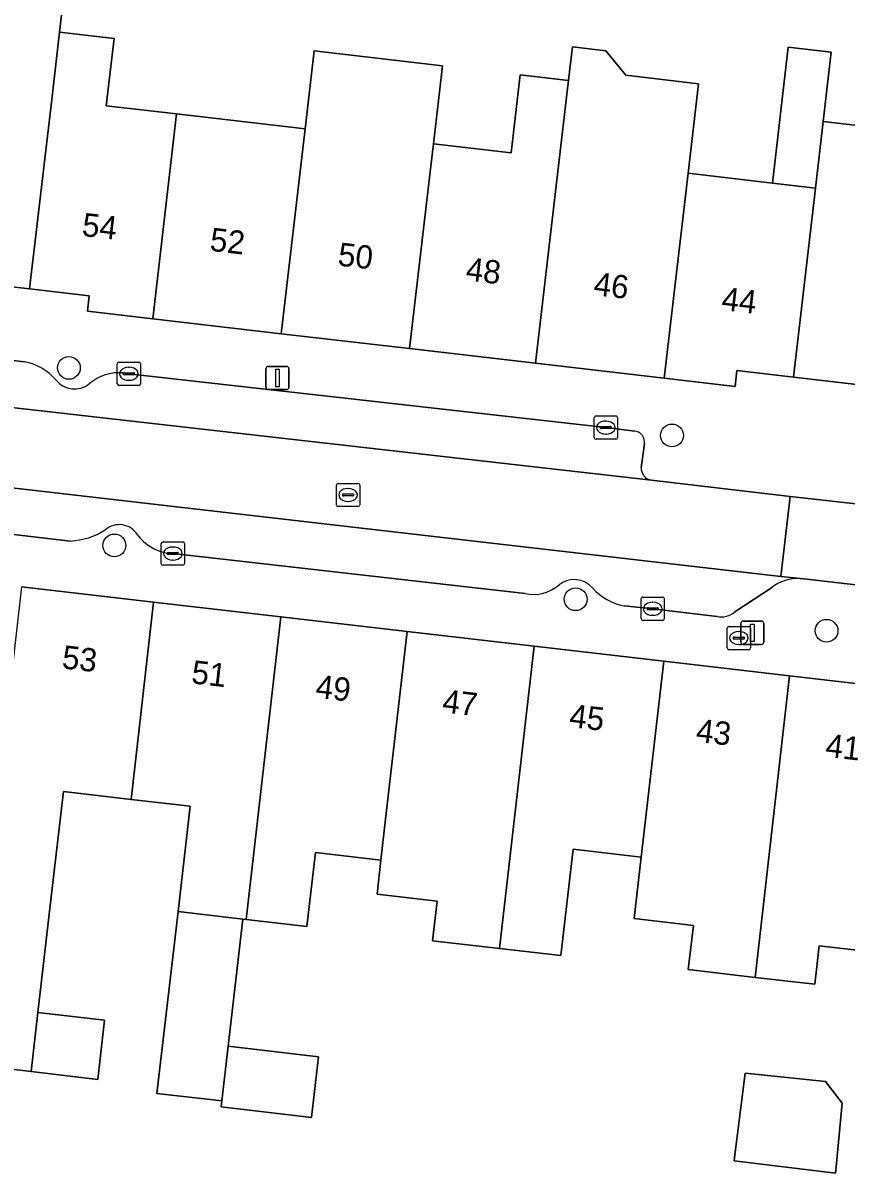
# Model space of a CAD drawing. Extents: x 161692 to 162379, y 380760 to 381678.
# Drawn here: x 161868.24 to 161903.6, y 381375.82 to 381425.22 of the extents above; entities that cross this region are included whole.
import ezdxf

# ---------------------------------------------------------------- set-up
doc = ezdxf.new("R2010")
doc.units = 0
for name, color, linetype in [('IMGEO_Boom', 7, 'Continuous'), ('IMGEO_Brandkraan', 7, 'Continuous'), ('IMGEO_Erf', 7, 'Continuous'), ('IMGEO_Kolk', 7, 'Continuous'), ('IMGEO_Lichtmast', 7, 'Continuous'), ('IMGEO_Pand', 7, 'Continuous'), ('IMGEO_Pand_nummerreeks', 7, 'Continuous'), ('IMGEO_Parkeervlak_open', 7, 'Continuous'), ('IMGEO_Rijbaan_lokaal_open', 7, 'Continuous'), ('IMGEO_Rioolput', 7, 'Continuous'), ('IMGEO_Voetpad_open', 7, 'Continuous')]:
    doc.layers.add(name, color=color, linetype=linetype)

msp = doc.modelspace()

# ---------------------------------------------------------------- linework, layer by layer
at = {"layer": 'IMGEO_Boom'}
for centre in [(161870.211, 381410.403), (161896.121, 381407.499), (161872.165, 381402.777), (161891.981, 381400.464), (161902.76, 381399.11)]:
    msp.add_circle(centre, 0.489, dxfattribs=at)
at = {"layer": 'IMGEO_Brandkraan'}
for p, q in [((161898.494, 381398.371), (161898.494, 381399.223)), ((161898.569, 381399.297), (161899.421, 381399.297)), ((161898.982, 381399.077), (161899.007, 381399.077)), ((161899.495, 381399.223), (161899.495, 381398.371)), ((161898.753, 381398.791), (161898.753, 381398.803)), ((161899.191, 381398.754), (161898.793, 381398.754)), ((161898.796, 381398.84), (161899.194, 381398.84)), ((161899.005, 381398.517), (161898.98, 381398.517)), ((161899.237, 381398.803), (161899.237, 381398.791)), ((161899.421, 381398.297), (161898.569, 381398.297))]:
    msp.add_line(p, q, dxfattribs=at)
for points in [[(161898.494, 381398.371), (161898.494, 381399.223)], [(161898.569, 381399.297), (161899.421, 381399.297)], [(161899.495, 381399.223), (161899.495, 381398.371)], [(161899.421, 381398.297), (161898.569, 381398.297)]]:
    msp.add_lwpolyline(points, dxfattribs=at)
for centre, radius, start, end in [((161898.571, 381399.221), 0.0765, 91.552, 178.448), ((161898.571, 381399.221), 0.0765, 91.552, 178.448), ((161899.419, 381399.221), 0.0765, 1.552, 88.448), ((161899.419, 381399.221), 0.0765, 1.552, 88.448), ((161898.793, 381398.8), 0.0403, 85.8775, 175.7526), ((161898.79, 381398.79), 0.0366, 178.938, 274.7102), ((161899.194, 381398.797), 0.043, 264.8664, 352.4533), ((161899.198, 381398.802), 0.0386, 1.7309, 96.639), ((161898.571, 381398.373), 0.0765, 181.552, 268.448), ((161898.571, 381398.373), 0.0765, 181.552, 268.448), ((161899.419, 381398.373), 0.0765, 271.552, 358.448), ((161899.419, 381398.373), 0.0765, 271.552, 358.448)]:
    msp.add_arc(centre, radius, start, end, dxfattribs=at)
for centre, major_axis, ratio, start_param, end_param in [((161898.981, 381398.797), (-0.387, 0.002), 0.722429, 4.712389, 7.853982), ((161899.006, 381398.797), (-0.39, 0.002), 0.717154, 1.570796, 4.712389)]:
    msp.add_ellipse(centre, major_axis=major_axis, ratio=ratio, start_param=start_param, end_param=end_param, dxfattribs=at)
at = {"layer": 'IMGEO_Erf'}
for points in [[(161870.722, 381432.685), (161869.807, 381424.816), (161872.151, 381424.544), (161871.816, 381421.661), (161874.839, 381421.31), (161880.359, 381420.669), (161880.749, 381424.017), (161886.262, 381423.376), (161885.872, 381420.029), (161889.213, 381419.641), (161889.601, 381422.988), (161891.674, 381422.747), (161891.733, 381423.252), (161891.842, 381424.189), (161893.278, 381424.022), (161894.138, 381422.973), (161897.26, 381422.61), (161896.812, 381418.759), (161900.436, 381418.338), (161901.114, 381424.178), (161902.96, 381423.964), (161902.614, 381420.985), (161907.924, 381420.369)], [(161905.321, 381385.248), (161902.447, 381385.58), (161902.256, 381383.926), (161899.696, 381384.222), (161896.821, 381384.555), (161897.04, 381386.451), (161894.501, 381386.744), (161894.802, 381389.384), (161891.877, 381389.723), (161891.348, 381385.157), (161888.713, 381385.462), (161885.831, 381385.796), (161886.027, 381387.493), (161883.448, 381387.792), (161883.616, 381389.255), (161880.801, 381389.58), (161880.433, 381386.404), (161877.827, 381386.706), (161877.685, 381386.722), (161877.054, 381381.264), (161880.94, 381380.813), (161880.637, 381378.203), (161876.751, 381378.654), (161876.781, 381378.914), (161873.996, 381379.236), (161874.9, 381387.045), (161875.424, 381391.571), (161872.88, 381391.865), (161869.978, 381392.201), (161869.454, 381387.674), (161868.879, 381382.71), (161871.743, 381382.378), (161871.449, 381379.84), (161868.586, 381380.179), (161865.833, 381380.505)]]:
    msp.add_lwpolyline(points, dxfattribs=at)
msp.add_lwpolyline([(161898.792, 381376.334), (161898.826, 381376.604), (161898.91, 381377.277), (161899.263, 381380.101), (161902.715, 381379.751), (161903.428, 381378.818), (161903.173, 381376.09), (161903.147, 381375.818)], close=True, dxfattribs=at)
at = {"layer": 'IMGEO_Kolk'}
for p, q in [((161872.288, 381409.722), (161872.288, 381410.574)), ((161872.363, 381410.648), (161873.215, 381410.648)), ((161872.776, 381410.428), (161872.801, 381410.428)), ((161873.289, 381410.574), (161873.289, 381409.722)), ((161872.547, 381410.142), (161872.547, 381410.154)), ((161872.985, 381410.105), (161872.587, 381410.105)), ((161872.59, 381410.191), (161872.988, 381410.191)), ((161872.799, 381409.868), (161872.774, 381409.868)), ((161873.031, 381410.154), (161873.031, 381410.142)), ((161873.215, 381409.648), (161872.363, 381409.648)), ((161892.858, 381408.336), (161893.71, 381408.336)), ((161892.783, 381407.41), (161892.783, 381408.262)), ((161893.042, 381407.83), (161893.042, 381407.842)), ((161893.085, 381407.879), (161893.483, 381407.879)), ((161893.271, 381408.116), (161893.296, 381408.116)), ((161893.526, 381407.842), (161893.526, 381407.83)), ((161893.784, 381408.262), (161893.784, 381407.41)), ((161893.71, 381407.336), (161892.858, 381407.336)), ((161893.48, 381407.793), (161893.082, 381407.793)), ((161893.294, 381407.556), (161893.269, 381407.556)), ((161874.255, 381402.927), (161875.107, 381402.927)), ((161874.18, 381402.001), (161874.18, 381402.853)), ((161874.439, 381402.421), (161874.439, 381402.433)), ((161874.877, 381402.384), (161874.479, 381402.384)), ((161874.482, 381402.47), (161874.88, 381402.47)), ((161874.668, 381402.707), (161874.693, 381402.707)), ((161874.923, 381402.433), (161874.923, 381402.421)), ((161875.181, 381402.853), (161875.181, 381402.001)), ((161875.107, 381401.927), (161874.255, 381401.927)), ((161874.691, 381402.147), (161874.666, 381402.147)), ((161894.791, 381399.63), (161894.791, 381400.482)), ((161894.866, 381400.556), (161895.718, 381400.556)), ((161895.792, 381400.482), (161895.792, 381399.63)), ((161895.05, 381400.05), (161895.05, 381400.062)), ((161895.488, 381400.013), (161895.09, 381400.013)), ((161895.093, 381400.099), (161895.491, 381400.099)), ((161895.279, 381400.336), (161895.304, 381400.336)), ((161895.534, 381400.062), (161895.534, 381400.05)), ((161895.718, 381399.556), (161894.866, 381399.556)), ((161895.302, 381399.776), (161895.277, 381399.776))]:
    msp.add_line(p, q, dxfattribs=at)
for points in [[(161872.288, 381409.722), (161872.288, 381410.574)], [(161872.363, 381410.648), (161873.215, 381410.648)], [(161873.289, 381410.574), (161873.289, 381409.722)], [(161873.215, 381409.648), (161872.363, 381409.648)], [(161892.858, 381408.336), (161893.71, 381408.336)], [(161892.783, 381407.41), (161892.783, 381408.262)], [(161893.784, 381408.262), (161893.784, 381407.41)], [(161893.71, 381407.336), (161892.858, 381407.336)], [(161874.255, 381402.927), (161875.107, 381402.927)], [(161874.18, 381402.001), (161874.18, 381402.853)], [(161875.181, 381402.853), (161875.181, 381402.001)], [(161875.107, 381401.927), (161874.255, 381401.927)], [(161894.791, 381399.63), (161894.791, 381400.482)], [(161894.866, 381400.556), (161895.718, 381400.556)], [(161895.792, 381400.482), (161895.792, 381399.63)], [(161895.718, 381399.556), (161894.866, 381399.556)]]:
    msp.add_lwpolyline(points, dxfattribs=at)
for centre, radius, start, end in [((161872.365, 381410.572), 0.0765, 91.552, 178.448), ((161872.365, 381410.572), 0.0765, 91.552, 178.448), ((161873.213, 381410.572), 0.0765, 1.552, 88.448), ((161873.213, 381410.572), 0.0765, 1.552, 88.448), ((161872.587, 381410.151), 0.0403, 85.8775, 175.7526), ((161872.584, 381410.141), 0.0366, 178.938, 274.7102), ((161872.988, 381410.148), 0.043, 264.8664, 352.4533), ((161872.992, 381410.153), 0.0386, 1.7309, 96.639), ((161872.365, 381409.724), 0.0765, 181.552, 268.448), ((161872.365, 381409.724), 0.0765, 181.552, 268.448), ((161873.213, 381409.724), 0.0765, 271.552, 358.448), ((161873.213, 381409.724), 0.0765, 271.552, 358.448), ((161892.86, 381408.26), 0.0765, 91.552, 178.448), ((161892.86, 381408.26), 0.0765, 91.552, 178.448), ((161893.708, 381408.26), 0.0765, 1.552, 88.448), ((161893.708, 381408.26), 0.0765, 1.552, 88.448), ((161893.082, 381407.839), 0.0403, 85.8775, 175.7526), ((161893.079, 381407.829), 0.0366, 178.938, 274.7102), ((161893.483, 381407.836), 0.043, 264.8664, 352.4533), ((161893.487, 381407.841), 0.0386, 1.7309, 96.639), ((161892.86, 381407.412), 0.0765, 181.552, 268.448), ((161892.86, 381407.412), 0.0765, 181.552, 268.448), ((161893.708, 381407.412), 0.0765, 271.552, 358.448), ((161893.708, 381407.412), 0.0765, 271.552, 358.448), ((161874.257, 381402.851), 0.0765, 91.552, 178.448), ((161874.257, 381402.851), 0.0765, 91.552, 178.448), ((161875.105, 381402.851), 0.0765, 1.552, 88.448), ((161875.105, 381402.851), 0.0765, 1.552, 88.448), ((161874.479, 381402.43), 0.0403, 85.8775, 175.7526), ((161874.476, 381402.42), 0.0366, 178.938, 274.7102), ((161874.88, 381402.427), 0.043, 264.8664, 352.4533), ((161874.884, 381402.432), 0.0386, 1.7309, 96.639), ((161874.257, 381402.003), 0.0765, 181.552, 268.448), ((161874.257, 381402.003), 0.0765, 181.552, 268.448), ((161875.105, 381402.003), 0.0765, 271.552, 358.448), ((161875.105, 381402.003), 0.0765, 271.552, 358.448), ((161894.868, 381400.48), 0.0765, 91.552, 178.448), ((161894.868, 381400.48), 0.0765, 91.552, 178.448), ((161895.716, 381400.48), 0.0765, 1.552, 88.448), ((161895.716, 381400.48), 0.0765, 1.552, 88.448), ((161895.09, 381400.059), 0.0403, 85.8775, 175.7526), ((161895.087, 381400.049), 0.0366, 178.938, 274.7102), ((161895.491, 381400.056), 0.043, 264.8664, 352.4533), ((161895.495, 381400.061), 0.0386, 1.7309, 96.639), ((161894.868, 381399.632), 0.0765, 181.552, 268.448), ((161894.868, 381399.632), 0.0765, 181.552, 268.448), ((161895.716, 381399.632), 0.0765, 271.552, 358.448), ((161895.716, 381399.632), 0.0765, 271.552, 358.448)]:
    msp.add_arc(centre, radius, start, end, dxfattribs=at)
for centre, major_axis, ratio, start_param, end_param in [((161872.775, 381410.148), (-0.387, 0.002), 0.722429, 4.712389, 7.853982), ((161872.8, 381410.148), (-0.39, 0.002), 0.717154, 1.570796, 4.712389), ((161893.27, 381407.836), (-0.387, 0.002), 0.722429, 4.712389, 7.853982), ((161893.295, 381407.836), (-0.39, 0.002), 0.717154, 1.570796, 4.712389), ((161874.667, 381402.427), (-0.387, 0.002), 0.722429, 4.712389, 7.853982), ((161874.692, 381402.427), (-0.39, 0.002), 0.717154, 1.570796, 4.712389), ((161895.278, 381400.056), (-0.387, 0.002), 0.722429, 4.712389, 7.853982), ((161895.303, 381400.056), (-0.39, 0.002), 0.717154, 1.570796, 4.712389)]:
    msp.add_ellipse(centre, major_axis=major_axis, ratio=ratio, start_param=start_param, end_param=end_param, dxfattribs=at)
at = {"layer": 'IMGEO_Lichtmast'}
for p, q in [((161878.677, 381409.567), (161878.677, 381410.367)), ((161878.677, 381410.367), (161878.677, 381409.567)), ((161878.777, 381410.467), (161879.567, 381410.467)), ((161879.567, 381410.467), (161878.777, 381410.467)), ((161879.667, 381410.367), (161879.667, 381409.567)), ((161879.667, 381409.567), (161879.667, 381410.367)), ((161879.567, 381409.467), (161878.777, 381409.467)), ((161878.777, 381409.467), (161879.567, 381409.467)), ((161899.075, 381398.623), (161899.075, 381399.423)), ((161899.075, 381399.423), (161899.075, 381398.623)), ((161899.175, 381399.523), (161899.965, 381399.523)), ((161899.965, 381399.523), (161899.175, 381399.523)), ((161900.065, 381399.423), (161900.065, 381398.623)), ((161900.065, 381398.623), (161900.065, 381399.423)), ((161899.965, 381398.523), (161899.175, 381398.523)), ((161899.175, 381398.523), (161899.965, 381398.523))]:
    msp.add_line(p, q, dxfattribs=at)
for points in [[(161879.097, 381410.342), (161879.247, 381410.342), (161879.247, 381409.592), (161879.097, 381409.592), (161879.097, 381410.342)], [(161899.495, 381399.398), (161899.645, 381399.398), (161899.645, 381398.648), (161899.495, 381398.648), (161899.495, 381399.398)]]:
    msp.add_lwpolyline(points, dxfattribs=at)
for centre, start, end in [((161878.777, 381410.367), 90, 180), ((161878.777, 381410.367), 90, 180), ((161879.567, 381410.367), 0, 90), ((161879.567, 381410.367), 360, 90), ((161878.777, 381409.567), 180, 270), ((161878.777, 381409.567), 180, 270), ((161879.567, 381409.567), 270, 0), ((161879.567, 381409.567), 270, 0), ((161899.175, 381399.423), 90, 180), ((161899.175, 381399.423), 90, 180), ((161899.965, 381399.423), 0, 90), ((161899.965, 381399.423), 360, 90), ((161899.175, 381398.623), 180, 270), ((161899.175, 381398.623), 180, 270), ((161899.965, 381398.623), 270, 0), ((161899.965, 381398.623), 270, 0)]:
    msp.add_arc(centre, 0.1, start, end, dxfattribs=at)
at = {"layer": 'IMGEO_Pand'}
for points in [[(161869.807, 381424.816), (161870.722, 381432.685), (161867.793, 381433.025), (161867.205, 381427.969), (161864.766, 381428.252), (161864.104, 381422.556), (161863.158, 381414.417), (161868.525, 381413.793), (161869.472, 381421.933)], [(161874.839, 381421.31), (161871.816, 381421.661), (161872.151, 381424.544), (161869.807, 381424.816), (161869.472, 381421.933), (161868.525, 381413.793), (161871.086, 381413.496), (161871.009, 381412.835), (161873.815, 381412.509)], [(161896.812, 381418.759), (161897.26, 381422.61), (161894.138, 381422.973), (161893.278, 381424.022), (161891.842, 381424.189), (161891.733, 381423.252), (161891.674, 381422.747), (161891.62, 381422.28), (161890.261, 381410.6), (161895.789, 381409.958)], [(161900.436, 381418.338), (161902.282, 381418.124), (161902.614, 381420.985), (161902.96, 381423.964), (161901.114, 381424.178)], [(161885.872, 381420.029), (161886.262, 381423.376), (161880.749, 381424.017), (161880.359, 381420.669), (161879.335, 381411.868), (161884.848, 381411.228), (161885.759, 381419.061)], [(161891.674, 381422.747), (161889.601, 381422.988), (161889.213, 381419.641), (161885.872, 381420.029), (161885.759, 381419.061), (161884.848, 381411.228), (161890.261, 381410.6), (161891.62, 381422.28)], [(161879.335, 381411.868), (161880.359, 381420.669), (161874.839, 381421.31), (161873.815, 381412.509)], [(161902.282, 381418.124), (161901.337, 381410.001), (161906.648, 381409.384), (161907.592, 381417.508), (161907.924, 381420.369), (161902.614, 381420.985)], [(161902.282, 381418.124), (161900.436, 381418.338), (161896.812, 381418.759), (161895.789, 381409.958), (161898.829, 381409.605), (161898.908, 381410.283), (161901.337, 381410.001)], [(161869.978, 381392.201), (161872.88, 381391.865), (161873.848, 381400.341), (161868.173, 381400.998), (161866.688, 381387.994), (161866.101, 381382.851), (161865.833, 381380.505), (161868.586, 381380.179), (161868.879, 381382.71), (161869.454, 381387.674)], [(161879.311, 381399.709), (161873.848, 381400.341), (161872.88, 381391.865), (161875.424, 381391.571), (161874.9, 381387.045), (161877.685, 381386.722), (161877.827, 381386.706)], [(161884.738, 381399.081), (161879.311, 381399.709), (161877.827, 381386.706), (161880.433, 381386.404), (161880.801, 381389.58), (161883.616, 381389.255), (161883.775, 381390.65)], [(161890.196, 381398.45), (161884.738, 381399.081), (161883.775, 381390.65), (161883.616, 381389.255), (161883.448, 381387.792), (161886.027, 381387.493), (161885.831, 381385.796), (161888.713, 381385.462)], [(161888.713, 381385.462), (161891.348, 381385.157), (161891.877, 381389.723), (161894.802, 381389.384), (161895.764, 381397.806), (161890.196, 381398.45)], [(161901.175, 381397.18), (161895.764, 381397.806), (161894.802, 381389.384), (161894.501, 381386.744), (161897.04, 381386.451), (161896.821, 381384.555), (161899.696, 381384.222)], [(161906.612, 381396.55), (161901.175, 381397.18), (161899.696, 381384.222), (161902.256, 381383.926), (161902.447, 381385.58), (161905.321, 381385.248), (161905.646, 381388.092)], [(161877.685, 381386.722), (161874.9, 381387.045), (161873.996, 381379.236), (161876.781, 381378.914), (161877.054, 381381.264)], [(161868.879, 381382.71), (161868.586, 381380.179), (161871.449, 381379.84), (161871.743, 381382.378)], [(161877.054, 381381.264), (161876.781, 381378.914), (161876.751, 381378.654), (161880.637, 381378.203), (161880.94, 381380.813)], [(161898.792, 381376.334), (161903.147, 381375.818), (161903.173, 381376.09), (161903.428, 381378.818), (161902.715, 381379.751), (161899.263, 381380.101), (161898.91, 381377.277), (161898.826, 381376.604)]]:
    msp.add_lwpolyline(points, close=True, dxfattribs=at)
at = {"layer": 'IMGEO_Parkeervlak_open'}
for points in [[(161859.876, 381411.344), (161858.18, 381410.038), (161857.4, 381409.877), (161895.242, 381405.574)], [(161868.306, 381410.664), (161861.855, 381411.4), (161860.627, 381411.544)], [(161894.523, 381407.689), (161893.284, 381407.834), (161872.789, 381410.147), (161872.555, 381410.183)], [(161894.793, 381406.122), (161894.936, 381407.135)], [(161901.631, 381401.358), (161900.802, 381401.436), (161857.93, 381406.381)], [(161860.634, 381404.069), (161860.872, 381404.054), (161870.275, 381402.964)], [(161874.462, 381402.441), (161874.681, 381402.429), (161889.809, 381400.713)], [(161898.821, 381399.919), (161900.394, 381400.954)], [(161894.061, 381400.186), (161895.292, 381400.057), (161898.064, 381399.719)]]:
    msp.add_lwpolyline(points, dxfattribs=at)
for centre, radius, start, end in [((161867.913, 381408.432), 2.266, 39.5077, 80.0057), ((161870.454, 381410.518), 1.022, 219.0894, 307.8141), ((161872.354, 381408.274), 1.92, 83.9863, 131.5256), ((161894.464, 381407.214), 0.478, 350.4388, 82.9693), ((161895.337, 381406.11), 0.544, 178.7056, 259.9529), ((161870.106, 381406.089), 3.13, 273.0886, 302.24), ((161872.378, 381402.758), 0.911, 31.5674, 131.3467), ((161874.782, 381404.443), 2.027, 216.5707, 260.911), ((161890.18, 381402.308), 1.637, 256.9003, 311.6887), ((161891.915, 381400.262), 1.047, 40.2492, 128.1334), ((161894.475, 381402.509), 2.36, 221.7484, 259.9043), ((161901.585, 381399.404), 1.955, 88.6432, 127.5305), ((161898.231, 381400.619), 0.915, 259.4824, 310.1164)]:
    msp.add_arc(centre, radius, start, end, dxfattribs=at)
at = {"layer": 'IMGEO_Rijbaan_lokaal_open'}
for points in [[(161895.242, 381405.574), (161857.4, 381409.877), (161854.636, 381410.238), (161854.089, 381410.284), (161853.694, 381406.835), (161854.44, 381406.749), (161857.687, 381406.409), (161857.93, 381406.381), (161900.802, 381401.436), (161901.191, 381404.882)], [(161906.162, 381404.303), (161904.792, 381404.483), (161901.191, 381404.882), (161900.802, 381401.436), (161901.631, 381401.358), (161901.907, 381401.332), (161905.382, 381400.926), (161905.689, 381400.892)]]:
    msp.add_lwpolyline(points, close=True, dxfattribs=at)
at = {"layer": 'IMGEO_Rioolput'}
for p, q in [((161881.703, 381404.516), (161881.703, 381405.368)), ((161881.778, 381405.442), (161882.63, 381405.442)), ((161882.704, 381405.368), (161882.704, 381404.516)), ((161881.962, 381404.936), (161881.962, 381404.948)), ((161882.4, 381404.899), (161882.002, 381404.899)), ((161882.005, 381404.985), (161882.403, 381404.985)), ((161882.191, 381405.222), (161882.216, 381405.222)), ((161882.446, 381404.948), (161882.446, 381404.936)), ((161882.63, 381404.442), (161881.778, 381404.442)), ((161882.214, 381404.662), (161882.189, 381404.662))]:
    msp.add_line(p, q, dxfattribs=at)
for points in [[(161881.703, 381404.516), (161881.703, 381405.368)], [(161881.778, 381405.442), (161882.63, 381405.442)], [(161882.704, 381405.368), (161882.704, 381404.516)], [(161882.63, 381404.442), (161881.778, 381404.442)]]:
    msp.add_lwpolyline(points, dxfattribs=at)
for centre, radius, start, end in [((161881.78, 381405.366), 0.0765, 91.552, 178.448), ((161881.78, 381405.366), 0.0765, 91.552, 178.448), ((161882.628, 381405.366), 0.0765, 1.552, 88.448), ((161882.628, 381405.366), 0.0765, 1.552, 88.448), ((161882.002, 381404.945), 0.0403, 85.8775, 175.7526), ((161881.999, 381404.935), 0.0366, 178.938, 274.7102), ((161882.403, 381404.942), 0.043, 264.8664, 352.4533), ((161882.407, 381404.947), 0.0386, 1.7309, 96.639), ((161881.78, 381404.518), 0.0765, 181.552, 268.448), ((161881.78, 381404.518), 0.0765, 181.552, 268.448), ((161882.628, 381404.518), 0.0765, 271.552, 358.448), ((161882.628, 381404.518), 0.0765, 271.552, 358.448)]:
    msp.add_arc(centre, radius, start, end, dxfattribs=at)
for centre, major_axis, ratio, start_param, end_param in [((161882.19, 381404.942), (-0.387, 0.002), 0.722429, 4.712389, 7.853982), ((161882.215, 381404.942), (-0.39, 0.002), 0.717154, 1.570796, 4.712389)]:
    msp.add_ellipse(centre, major_axis=major_axis, ratio=ratio, start_param=start_param, end_param=end_param, dxfattribs=at)
at = {"layer": 'IMGEO_Voetpad_open'}
for points in [[(161926.826, 381406.339), (161923.396, 381406.735), (161917.612, 381407.406), (161914.794, 381407.733), (161914.875, 381408.429), (161912.212, 381408.738), (161906.648, 381409.384), (161901.337, 381410.001), (161898.908, 381410.283), (161898.829, 381409.605), (161895.789, 381409.958), (161890.261, 381410.6), (161884.848, 381411.228), (161879.335, 381411.868), (161873.815, 381412.509), (161871.009, 381412.835), (161871.086, 381413.496), (161868.525, 381413.793), (161863.158, 381414.417)], [(161860.627, 381411.544), (161861.855, 381411.4), (161868.306, 381410.664)], [(161872.555, 381410.183), (161872.789, 381410.147), (161893.284, 381407.834), (161894.523, 381407.689)], [(161894.936, 381407.135), (161894.793, 381406.122)], [(161895.242, 381405.574), (161901.191, 381404.882), (161904.792, 381404.483)], [(161870.275, 381402.964), (161860.872, 381404.054), (161860.634, 381404.069)], [(161889.809, 381400.713), (161874.681, 381402.429), (161874.462, 381402.441)], [(161868.173, 381400.998), (161873.848, 381400.341), (161879.311, 381399.709), (161884.738, 381399.081), (161890.196, 381398.45), (161895.764, 381397.806), (161901.175, 381397.18), (161906.612, 381396.55), (161912.282, 381395.894), (161917.607, 381395.278), (161923.109, 381394.642), (161928.431, 381394.026), (161934.034, 381393.378), (161939.512, 381392.744), (161944.835, 381392.128), (161950.299, 381391.496), (161957.825, 381390.625), (161958.329, 381394.82)], [(161900.394, 381400.954), (161898.821, 381399.919)], [(161905.689, 381400.892), (161905.382, 381400.926), (161901.907, 381401.332), (161901.631, 381401.358)], [(161898.064, 381399.719), (161895.292, 381400.057), (161894.061, 381400.186)]]:
    msp.add_lwpolyline(points, dxfattribs=at)
for centre, radius, start, end in [((161867.913, 381408.432), 2.266, 39.5077, 80.0057), ((161870.454, 381410.518), 1.022, 219.0894, 307.8141), ((161872.354, 381408.274), 1.92, 83.9863, 131.5256), ((161894.464, 381407.214), 0.478, 350.4388, 82.9693), ((161895.337, 381406.11), 0.544, 178.7056, 259.9529), ((161870.106, 381406.089), 3.13, 273.0886, 302.24), ((161872.378, 381402.758), 0.911, 31.5674, 131.3467), ((161874.782, 381404.443), 2.027, 216.5707, 260.911), ((161890.18, 381402.308), 1.637, 256.9003, 311.6887), ((161891.915, 381400.262), 1.047, 40.2492, 128.1334), ((161894.475, 381402.509), 2.36, 221.7484, 259.9043), ((161901.585, 381399.404), 1.955, 88.6432, 127.5305), ((161898.231, 381400.619), 0.915, 259.4824, 310.1164)]:
    msp.add_arc(centre, radius, start, end, dxfattribs=at)

# ---------------------------------------------------------------- texts
at = {"layer": 'IMGEO_Pand_nummerreeks'}
for s, rotation, p in [('54', 353.3938, (161870.741, 381416.074)), ('52', 353.3948, (161876.233, 381415.438)), ('50', 353.3938, (161881.735, 381414.8)), ('48', 353.3938, (161887.23, 381414.164)), ('46', 353.3938, (161892.722, 381413.529)), ('44', 353.3938, (161898.217, 381412.892)), ('53', 353.3995, (161869.881, 381397.499)), ('51', 353.3995, (161875.442, 381396.856)), ('49', 353.3995, (161880.777, 381396.238)), ('47', 353.3995, (161886.225, 381395.608)), ('45', 353.4003, (161891.673, 381394.978)), ('43', 353.3995, (161897.121, 381394.347)), ('41', 353.3995, (161902.682, 381393.704))]:
    msp.add_text(s, height=1, rotation=rotation, dxfattribs=at).set_placement(p)

doc.saveas('drawing.dxf')
